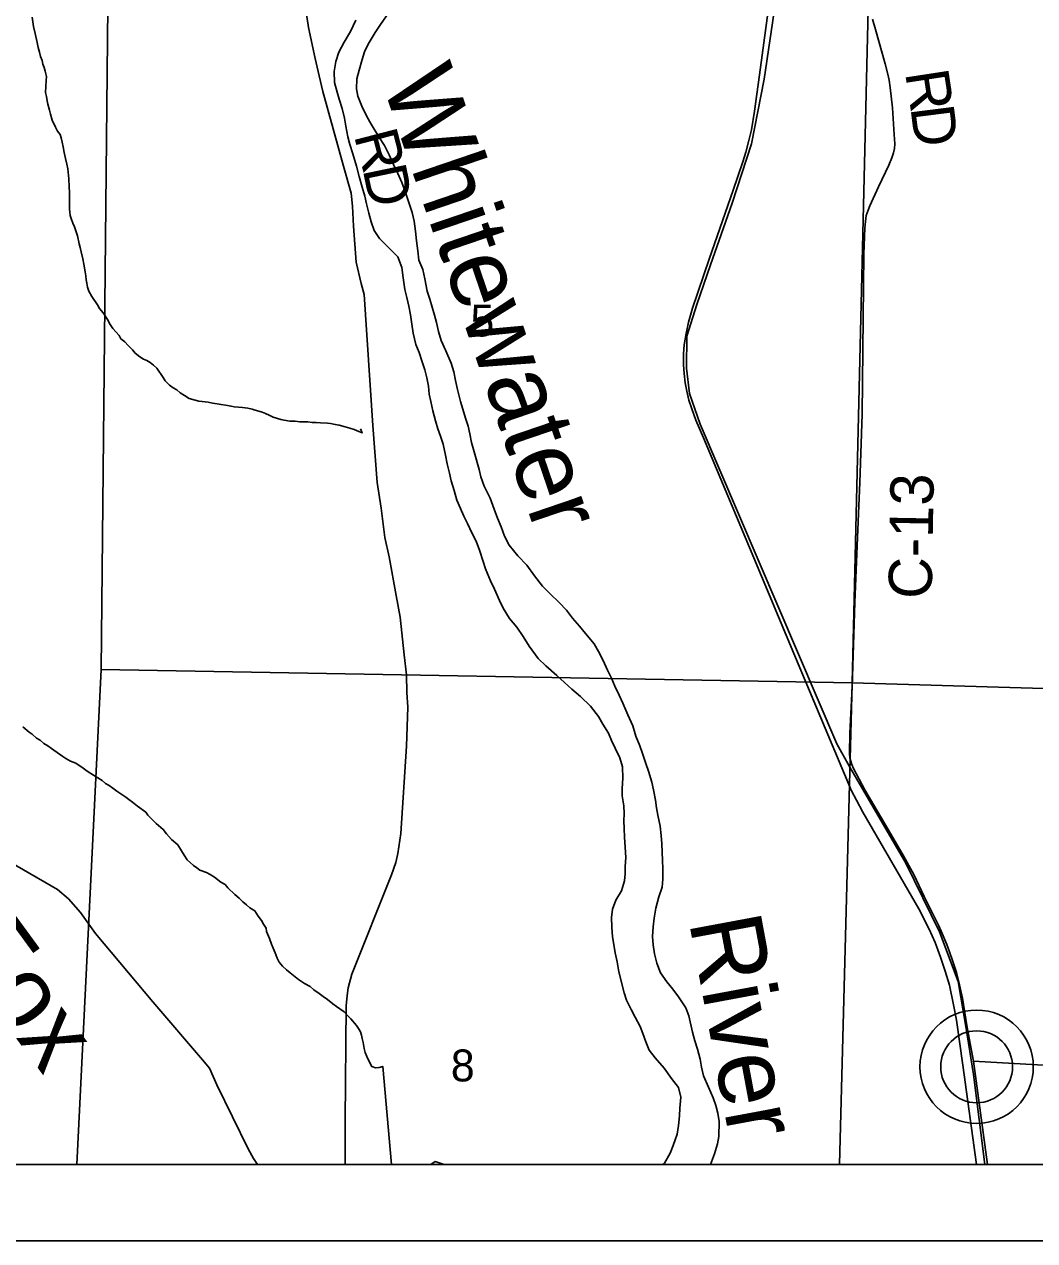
# Model space of a CAD drawing. Extents: x -7.5 to 26.5, y 3.5 to 25.5.
# Drawn here: x -4.425 to -3.099, y 17.5 to 19.097 of the extents above; entities that cross this region are included whole.
import ezdxf

# ---------------------------------------------------------------- set-up
doc = ezdxf.new("R2010")
doc.units = 0
for name, color, linetype in [('GM_X_Corporation', 7, 'Continuous'), ('GM_X_County_Road', 7, 'Continuous'), ('GM_X_County_Road_Text', 7, 'Continuous'), ('GM_X_Minor_River', 7, 'Continuous'), ('GM_X_Minor_River_Text', 7, 'Continuous'), ('GM_X_Rail_Line', 7, 'Continuous'), ('GM_X_Section_Text', 7, 'Continuous'), ('GM_X_Unincorporated', 7, 'Continuous'), ('GM_X_Unincorporated_Location', 7, 'Continuous'), ('SH_Data', 7, 'Continuous')]:
    doc.layers.add(name, color=color, linetype=linetype)

msp = doc.modelspace()

# ---------------------------------------------------------------- linework, layer by layer
at = {"layer": 'GM_X_Corporation'}
for points in [[(-5.2848, 19.2392), (-5.3003, 18.6476), (-5.3247, 17.7117), (-5.3276, 17.6), (1.4431, 17.6), (1.4431, 24.4)], [(-5.2848, 19.2392), (-5.3003, 18.6476), (-5.3247, 17.7117), (-5.3276, 17.6), (-2.0482, 17.6)]]:
    msp.add_lwpolyline(points, dxfattribs=at)
for points in [[(-4.3152, 19.2075), (-3.3161, 19.1909), (-3.3388, 18.2326), (-4.3246, 18.2499)], [(-2.3216, 19.1609), (-2.3477, 18.203), (-3.3388, 18.2326), (-3.3161, 19.1909)], [(-4.3564, 17.6), (-3.3553, 17.6), (-3.3388, 18.2326), (-4.3246, 18.2499)], [(-3.3553, 17.6), (-2.3653, 17.6), (-2.3477, 18.203), (-3.3388, 18.2326)]]:
    msp.add_lwpolyline(points, close=True, dxfattribs=at)
at = {"layer": 'GM_X_County_Road'}
for points in [[(-4.053, 19.0957), (-4.0615, 19.153)], [(-3.161, 17.6), (-3.1793, 17.7357), (-3.1876, 17.7797), (-3.194, 17.8183), (-3.1977, 17.8361), (-3.2017, 17.8522), (-3.2063, 17.8665), (-3.2107, 17.879), (-3.2145, 17.889), (-3.2218, 17.9065), (-3.2249, 17.9133), (-3.2339, 17.9318), (-3.2439, 17.952), (-3.2579, 17.9806), (-3.2714, 18.0053), (-3.2945, 18.045), (-3.3058, 18.0643), (-3.3219, 18.092), (-3.3369, 18.1197), (-3.3392, 18.1251), (-3.3415, 18.134), (-3.3422, 18.1397), (-3.3415, 18.1662), (-3.3387, 18.2268), (-3.3351, 18.3379), (-3.3308, 18.4441), (-3.3287, 18.4955), (-3.3254, 18.5853), (-3.3232, 18.7955), (-3.322, 18.8294), (-3.3213, 18.8381), (-3.3203, 18.8459), (-3.3176, 18.8529), (-3.3153, 18.8586), (-3.304, 18.8835), (-3.2904, 18.9119), (-3.2865, 18.9218), (-3.2843, 18.9284), (-3.2831, 18.9339), (-3.2828, 18.9402), (-3.2833, 18.9524), (-3.2859, 18.9873), (-3.2887, 19.0139), (-3.2902, 19.0237), (-3.292, 19.0314), (-3.2953, 19.0451), (-3.3081, 19.0903), (-3.312, 19.1039)], [(-4.0043, 17.6), (-4.0044, 17.6576), (-4.003, 17.8082), (-4.0018, 17.8221), (-4.0003, 17.832), (-3.9956, 17.85), (-3.9433, 17.9803), (-3.9379, 17.9964), (-3.9352, 18.0085), (-3.9312, 18.0345), (-3.9239, 18.1492), (-3.9222, 18.2004), (-3.9234, 18.2198), (-3.9238, 18.2429), (-3.9267, 18.2692), (-3.9322, 18.3187), (-3.9373, 18.347), (-3.9465, 18.3977), (-3.9521, 18.423), (-3.9569, 18.4618), (-3.9622, 18.4954), (-3.968, 18.5704), (-3.9795, 18.7423), (-3.9832, 18.7568), (-3.9898, 18.7847), (-3.9932, 18.8319), (-3.9945, 18.8581), (-3.9966, 18.8753), (-4.0064, 18.9109), (-4.0334, 19.0086), (-4.0384, 19.0292), (-4.0437, 19.0522), (-4.0525, 19.0927), (-4.053, 19.0957)], [(-4.4798, 18.0177), (-4.382, 17.9609), (-4.3676, 17.949), (-4.3516, 17.9307), (-4.332, 17.9035), (-4.257, 17.8137), (-4.1917, 17.7375), (-4.1826, 17.7266), (-4.1727, 17.7046), (-4.1315, 17.6205), (-4.1248, 17.6078), (-4.1193, 17.6)], [(-3.1793, 17.7357), (-3.0798, 17.7302)]]:
    msp.add_lwpolyline(points, dxfattribs=at)
at = {"layer": 'GM_X_Minor_River'}
for points in [[(-4.4154, 19.1065), (-4.4136, 19.0939), (-4.4112, 19.0847), (-4.4086, 19.0732), (-4.4073, 19.0667), (-4.4056, 19.0602), (-4.4043, 19.0548), (-4.4022, 19.0494), (-4.4012, 19.0448), (-4.3995, 19.0402), (-4.3981, 19.0356), (-4.3965, 19.0283), (-4.397, 19.023), (-4.3976, 19.0075), (-4.3966, 19.0021), (-4.3957, 18.9964), (-4.3947, 18.9922), (-4.3923, 18.9841), (-4.3913, 18.9791), (-4.389, 18.9711), (-4.3847, 18.9618), (-4.3819, 18.9568), (-4.3786, 18.9521), (-4.3772, 18.9479), (-4.3759, 18.9421), (-4.3746, 18.936), (-4.373, 18.9287), (-4.3713, 18.9207), (-4.3697, 18.9134), (-4.3684, 18.9073), (-4.3669, 18.8939), (-4.3665, 18.8837), (-4.366, 18.876), (-4.3662, 18.8719), (-4.366, 18.8669), (-4.3664, 18.8544), (-4.3658, 18.8502), (-4.3652, 18.846), (-4.3642, 18.8418), (-4.3617, 18.836), (-4.3596, 18.831), (-4.3579, 18.826), (-4.3559, 18.8191), (-4.3536, 18.8087), (-4.3522, 18.8041), (-4.3509, 18.7984), (-4.3489, 18.7892), (-4.3473, 18.7819), (-4.3457, 18.772), (-4.3448, 18.7666), (-4.3442, 18.7617), (-4.3436, 18.7571), (-4.3426, 18.7517), (-4.3409, 18.7467), (-4.337, 18.7397), (-4.3294, 18.7285), (-4.3269, 18.7238), (-4.3218, 18.7183), (-4.3153, 18.7082), (-4.3135, 18.704), (-4.3092, 18.6977), (-4.3055, 18.6934), (-4.3011, 18.6883), (-4.2986, 18.6841), (-4.2935, 18.6801), (-4.2891, 18.6754), (-4.2836, 18.6695), (-4.2799, 18.6652), (-4.274, 18.6604), (-4.2692, 18.6572), (-4.2647, 18.6555), (-4.2602, 18.6531), (-4.2558, 18.6495), (-4.2517, 18.6456), (-4.2431, 18.6331), (-4.2406, 18.6289), (-4.235, 18.6234), (-4.2299, 18.6198), (-4.2254, 18.6169), (-4.221, 18.613), (-4.2154, 18.6098), (-4.2091, 18.6057), (-4.2012, 18.6036)], [(-3.9903, 19.1023), (-3.9971, 19.0877), (-4.0058, 19.0734), (-4.0126, 19.0603), (-4.0167, 19.0483), (-4.0185, 19.0351), (-4.0181, 19.0206), (-4.0147, 19.008), (-4.0123, 18.9985), (-4.008, 18.9866), (-4.005, 18.9736), (-4.0033, 18.9633), (-4.0007, 18.9492), (-3.9983, 18.9393), (-3.9944, 18.9271), (-3.9895, 18.9106), (-3.9857, 18.8972), (-3.9819, 18.8831), (-3.9784, 18.8712), (-3.9764, 18.8613), (-3.9733, 18.8491), (-3.9702, 18.8376), (-3.9663, 18.8262), (-3.9594, 18.8157), (-3.9461, 18.8025), (-3.935, 18.7916), (-3.93, 18.7778), (-3.9281, 18.7641), (-3.9259, 18.7488), (-3.9235, 18.7382), (-3.9208, 18.7267), (-3.9184, 18.7156), (-3.9168, 18.7031), (-3.9148, 18.6916), (-3.9114, 18.6768), (-3.9072, 18.666), (-3.9033, 18.6538), (-3.8998, 18.6434), (-3.897, 18.6327), (-3.895, 18.6217), (-3.8938, 18.6114), (-3.8918, 18.6019), (-3.889, 18.5893)], [(-3.8382, 18.5478), (-3.8406, 18.5592), (-3.8429, 18.5695), (-3.8465, 18.5798), (-3.85, 18.5917), (-3.8527, 18.6016), (-3.8569, 18.6173), (-3.8596, 18.6295), (-3.8616, 18.6406), (-3.8651, 18.652), (-3.8719, 18.6681), (-3.8783, 18.682), (-3.8818, 18.6938), (-3.8845, 18.7053), (-3.8869, 18.7152), (-3.8932, 18.7359), (-3.8964, 18.7466), (-3.8997, 18.7626), (-3.9025, 18.7752), (-3.9074, 18.7875), (-3.909, 18.7996), (-3.9106, 18.8126), (-3.9118, 18.8255), (-3.9137, 18.8385), (-3.9164, 18.8499), (-3.9207, 18.8629), (-3.9249, 18.8763), (-3.9298, 18.8893), (-3.9352, 18.9009), (-3.9406, 18.9128), (-3.9463, 18.9254), (-3.9525, 18.9377), (-3.9601, 18.9493), (-3.9703, 18.9659), (-3.9757, 18.9759), (-3.9826, 18.9897), (-3.9875, 19.0028), (-3.9892, 19.0123), (-3.9889, 19.0252), (-3.9859, 19.0369), (-3.9818, 19.0508), (-3.9788, 19.061), (-3.974, 19.0707), (-3.9649, 19.0861), (-3.9578, 19.0965), (-3.948, 19.1111)], [(-4.2012, 18.6036), (-4.1963, 18.6023), (-4.1921, 18.6017), (-4.1842, 18.6007), (-4.1785, 18.5997), (-4.1725, 18.5988), (-4.1672, 18.5978), (-4.1612, 18.5969), (-4.154, 18.5955), (-4.1498, 18.5949), (-4.1445, 18.5944), (-4.1389, 18.5938), (-4.1321, 18.5928), (-4.1264, 18.5915), (-4.1223, 18.5902), (-4.1174, 18.5889), (-4.1133, 18.5876), (-4.1088, 18.5859), (-4.1039, 18.5839), (-4.0987, 18.5814), (-4.0889, 18.578), (-4.0844, 18.5771), (-4.0768, 18.5761), (-4.07, 18.5758), (-4.0636, 18.5752), (-4.0533, 18.5749), (-4.0477, 18.5743), (-4.0424, 18.5741), (-4.0367, 18.5739), (-4.0276, 18.5732), (-4.0234, 18.5727), (-4.0174, 18.5717), (-4.0121, 18.5708), (-4.0042, 18.5686), (-3.9982, 18.5669), (-3.9926, 18.5648), (-3.9862, 18.5623), (-3.9821, 18.5606), (-3.9842, 18.566)], [(-3.889, 18.5893), (-3.8856, 18.5763), (-3.8824, 18.566), (-3.8793, 18.5564), (-3.8758, 18.5457), (-3.8727, 18.5312), (-3.8704, 18.5197), (-3.8673, 18.5075), (-3.8649, 18.4976), (-3.861, 18.485), (-3.8576, 18.472), (-3.8529, 18.4612), (-3.8486, 18.4513), (-3.8436, 18.4416), (-3.8378, 18.4294), (-3.8324, 18.4182), (-3.8278, 18.4067), (-3.8233, 18.3918), (-3.8201, 18.3822), (-3.8133, 18.3665), (-3.8083, 18.3554), (-3.8015, 18.3404), (-3.7968, 18.3304), (-3.7884, 18.3169), (-3.7789, 18.3053), (-3.7705, 18.2933), (-3.7628, 18.2806), (-3.7511, 18.2643), (-3.7408, 18.2546), (-3.7263, 18.2421), (-3.7163, 18.2327), (-3.7067, 18.2241), (-3.6952, 18.2143), (-3.6823, 18.2019), (-3.6716, 18.1883), (-3.6658, 18.1783), (-3.6585, 18.1664), (-3.6546, 18.1568), (-3.6499, 18.1468), (-3.6438, 18.1341), (-3.6403, 18.1223), (-3.6396, 18.1074), (-3.6407, 18.0938), (-3.6406, 18.0839), (-3.6386, 18.071), (-3.6381, 18.0607), (-3.6384, 18.0513), (-3.6379, 18.041), (-3.6374, 18.0296), (-3.6366, 18.0167), (-3.6358, 18.003), (-3.6365, 17.9913), (-3.6367, 17.9818), (-3.6374, 17.9723), (-3.6415, 17.9595), (-3.649, 17.9472), (-3.6535, 17.9352), (-3.6545, 17.9242), (-3.6541, 17.9117), (-3.6533, 17.8987), (-3.6516, 17.8888), (-3.6496, 17.8778), (-3.6473, 17.866), (-3.645, 17.853), (-3.6381, 17.8255), (-3.6349, 17.8159), (-3.6288, 17.8036), (-3.6234, 17.7936), (-3.6169, 17.7813), (-3.6133, 17.7718), (-3.6094, 17.761), (-3.6052, 17.7503), (-3.5971, 17.7399), (-3.5853, 17.7263), (-3.5758, 17.7128), (-3.5666, 17.7011), (-3.5635, 17.6885), (-3.5647, 17.6738), (-3.5653, 17.6639), (-3.5668, 17.6514), (-3.5686, 17.6397), (-3.5735, 17.6251), (-3.5775, 17.6149), (-3.5851, 17.6018), (-3.587, 17.6)], [(-3.5245, 17.6), (-3.5196, 17.6138), (-3.5155, 17.627), (-3.5137, 17.6368), (-3.5132, 17.6565), (-3.5152, 17.6672), (-3.5176, 17.6775), (-3.5211, 17.6874), (-3.5272, 17.7016), (-3.5337, 17.7162), (-3.5364, 17.7277), (-3.5384, 17.7383), (-3.5418, 17.7513), (-3.545, 17.7624), (-3.5481, 17.7739), (-3.5529, 17.7952), (-3.5571, 17.8056), (-3.5666, 17.8203), (-3.5743, 17.8303), (-3.582, 17.84), (-3.5904, 17.8516), (-3.595, 17.8642), (-3.5981, 17.8768), (-3.6001, 17.8886), (-3.6006, 17.8993), (-3.5999, 17.9122), (-3.5988, 17.9235), (-3.5962, 17.9367), (-3.5924, 17.9514), (-3.5883, 17.9642), (-3.5873, 17.9748), (-3.5873, 17.9885), (-3.5878, 17.9991), (-3.5883, 18.0101), (-3.5884, 18.0211), (-3.5892, 18.0318), (-3.5908, 18.044), (-3.5939, 18.0585), (-3.5955, 18.0684), (-3.5968, 18.0783), (-3.5994, 18.092), (-3.6018, 18.1019), (-3.606, 18.1164), (-3.6095, 18.1264), (-3.6141, 18.1398), (-3.6173, 18.1497), (-3.6226, 18.1624), (-3.6268, 18.1758), (-3.6333, 18.1904), (-3.6397, 18.2057), (-3.6444, 18.2161), (-3.6501, 18.228), (-3.6544, 18.2383), (-3.6598, 18.2491), (-3.6656, 18.2618), (-3.6717, 18.2737), (-3.6775, 18.2837), (-3.6889, 18.2973), (-3.6966, 18.307), (-3.7058, 18.3174), (-3.7139, 18.3279), (-3.7235, 18.338), (-3.7353, 18.3493), (-3.7453, 18.3591), (-3.7559, 18.373), (-3.7658, 18.3869), (-3.7776, 18.3993), (-3.789, 18.4133), (-3.7951, 18.4248), (-3.7994, 18.4371), (-3.8044, 18.4486), (-3.8086, 18.4605), (-3.8139, 18.4747), (-3.8219, 18.4904), (-3.8261, 18.5027), (-3.8285, 18.5126), (-3.8347, 18.5355), (-3.8382, 18.5478)], [(-3.9433, 17.6), (-3.9549, 17.7287), (-3.9595, 17.7274), (-3.9645, 17.7268), (-3.9693, 17.7288), (-3.9722, 17.7343), (-3.9757, 17.7416), (-3.9778, 17.747), (-3.9792, 17.7524), (-3.9808, 17.76), (-3.9818, 17.7654), (-3.9827, 17.77), (-3.9841, 17.7742), (-3.9866, 17.7784), (-3.9895, 17.7827), (-3.9968, 17.7913), (-4.0008, 17.7953), (-4.0056, 17.8004), (-4.0156, 17.8076), (-4.0204, 17.8111), (-4.0274, 17.8167), (-4.033, 17.8207), (-4.0382, 17.8243), (-4.0452, 17.8295), (-4.0504, 17.8338), (-4.0575, 17.8375), (-4.0656, 17.8431), (-4.0723, 17.8483), (-4.0764, 17.8518), (-4.0815, 17.8558), (-4.0867, 17.8606), (-4.0911, 17.8656), (-4.0935, 17.8707), (-4.096, 17.878), (-4.0988, 17.8842), (-4.1009, 17.8895), (-4.1037, 17.8969), (-4.1075, 17.9061), (-4.1081, 17.9103), (-4.1114, 17.9157), (-4.1142, 17.9204), (-4.1186, 17.9262), (-4.1229, 17.9329), (-4.1296, 17.9369), (-4.134, 17.9408), (-4.1388, 17.9448), (-4.1436, 17.9495), (-4.1491, 17.9547), (-4.1583, 17.9633), (-4.1616, 17.9676), (-4.1675, 17.9709), (-4.1757, 17.9772), (-4.1816, 17.9809), (-4.1865, 17.9833), (-4.1951, 17.9866), (-4.1992, 17.9894), (-4.2036, 17.9926), (-4.2117, 17.9998), (-4.2157, 18.006), (-4.2193, 18.0118), (-4.224, 18.0196), (-4.2324, 18.0267), (-4.239, 18.0341), (-4.243, 18.04), (-4.2522, 18.0475), (-4.2566, 18.0519), (-4.2632, 18.0585), (-4.2661, 18.0628), (-4.2769, 18.0704), (-4.2835, 18.0756), (-4.2884, 18.0792), (-4.2924, 18.0823), (-4.3039, 18.0903), (-4.3095, 18.094), (-4.3143, 18.0975), (-4.3191, 18.1004), (-4.3232, 18.1043), (-4.3347, 18.1112), (-4.3429, 18.1164), (-4.3481, 18.1204), (-4.3577, 18.1268), (-4.3648, 18.1297), (-4.3708, 18.1329), (-4.3749, 18.1357), (-4.3793, 18.1389), (-4.3897, 18.1461), (-4.3945, 18.1497), (-4.3997, 18.1529), (-4.4049, 18.1569), (-4.4093, 18.1597), (-4.4152, 18.1652), (-4.4193, 18.1677), (-4.4274, 18.1748)], [(-3.8742, 17.6), (-3.8859, 17.6039), (-3.892, 17.6)]]:
    msp.add_lwpolyline(points, dxfattribs=at)
at = {"layer": 'GM_X_Rail_Line'}
for points in [[(-3.4242, 19.2265), (-3.4542, 19.0248), (-3.471, 18.9402), (-3.4962, 18.8622), (-3.5247, 18.7811), (-3.5427, 18.729), (-3.5558, 18.6876), (-3.5563, 18.6455), (-3.5523, 18.6122), (-3.5383, 18.5722), (-3.3589, 18.1525), (-3.3416, 18.1215), (-3.268, 17.9956), (-3.2242, 17.9055), (-3.1995, 17.8404), (-3.1895, 17.7812), (-3.1793, 17.7182), (-3.1644, 17.6)], [(-3.1756, 17.6), (-3.1933, 17.7303), (-3.2016, 17.7897), (-3.2054, 17.8096), (-3.2109, 17.8353), (-3.2166, 17.8539), (-3.2226, 17.8724), (-3.2297, 17.8914), (-3.2374, 17.9088), (-3.2512, 17.9358), (-3.2846, 17.9939), (-3.3245, 18.0628), (-3.3329, 18.0782), (-3.3393, 18.0908), (-3.374, 18.1728), (-3.4153, 18.2707), (-3.4676, 18.3963), (-3.5338, 18.554), (-3.5438, 18.5771), (-3.549, 18.592), (-3.5529, 18.6034), (-3.5559, 18.6151), (-3.5578, 18.6263), (-3.5594, 18.6384), (-3.56, 18.6498), (-3.56, 18.6642), (-3.5592, 18.6763), (-3.5567, 18.6909), (-3.5535, 18.7059), (-3.5482, 18.7244), (-3.5266, 18.7886), (-3.4949, 18.8791), (-3.4822, 18.9162), (-3.4782, 18.9292), (-3.4741, 18.9444), (-3.4709, 18.9583), (-3.4668, 18.9831), (-3.4591, 19.0404), (-3.4481, 19.1211)]]:
    msp.add_lwpolyline(points, dxfattribs=at)
at = {"layer": 'GM_X_Unincorporated'}
for radius in [0.0744, 0.0472]:
    msp.add_circle((-3.1752, 17.7283), radius, dxfattribs=at)
at = {"layer": 'GM_X_Unincorporated_Location'}
msp.add_line((-3.1752, 17.7283), (-3.1752, 17.7283), dxfattribs=at)
at = {"layer": 'SH_Data'}
for p, q in [((-5.3569, 17.6), (1.4431, 17.6)), ((-5.4569, 17.5), (1.5431, 17.5))]:
    msp.add_line(p, q, dxfattribs=at)

# ---------------------------------------------------------------- texts
at = {"layer": 'GM_X_County_Road_Text'}
for s, height, rotation, p in [('R', 0.0568, 278.7625, (-3.2693, 19.0334)), ('D', 0.0568, 277.2055, (-3.2622, 18.9877)), ('R', 0.0568, 284.5425, (-3.993, 18.9514)), ('D', 0.0568, 281.7766, (-3.9815, 18.9069)), ('C-13', 0.05682, 88.9708, (-3.2343, 18.3422))]:
    msp.add_text(s, height=height, rotation=rotation, dxfattribs=at).set_placement(p)
at = {"layer": 'GM_X_Minor_River_Text'}
for s, height, rotation, p in [('Whitewater', 0.0947, 288.8354, (-3.9567, 19.0219)), ('Fox', 0.09469, 306.1544, (-4.5244, 17.8863)), ('River', 0.09468, 280.5487, (-3.5531, 17.9193))]:
    msp.add_text(s, height=height, rotation=rotation, dxfattribs=at).set_placement(p)
at = {"layer": 'GM_X_Section_Text'}
for s, p in [('5', (-3.8397, 18.6871)), ('8', (-3.8655, 17.7091))]:
    msp.add_text(s, height=0.0419, rotation=0, dxfattribs=at).set_placement(p)

doc.saveas('drawing.dxf')
